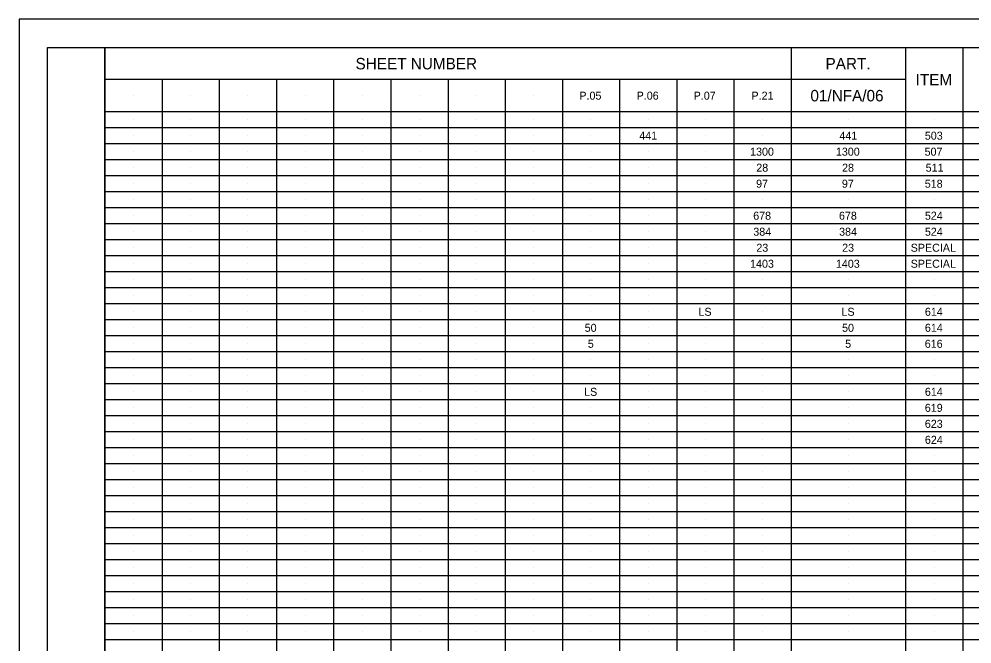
# Model space of a CAD drawing. Extents: x 0 to 34, y 0 to 22.
# Drawn here: x 0 to 16.66, y 11.07 to 22 of the extents above; entities that cross this region are included whole.
import ezdxf

# ---------------------------------------------------------------- set-up
doc = ezdxf.new("R2010")
doc.units = 0
for name, color, linetype in [('RD_P_Text', 7, 'Continuous'), ('SC_Scratch1', 7, 'Continuous'), ('SH_Border', 7, 'Continuous'), ('SH_Cut_Line', 7, 'Continuous'), ('SH_Data', 7, 'Continuous')]:
    doc.layers.add(name, color=color, linetype=linetype)

msp = doc.modelspace()

# ---------------------------------------------------------------- linework, layer by layer
at = {"layer": 'SC_Scratch1'}
for p, q in [((2, 20.66), (2, 20.66)), ((3, 20.66), (3, 20.66)), ((4, 20.66), (4, 20.66)), ((5, 20.66), (5, 20.66)), ((6, 20.66), (6, 20.66)), ((7, 20.66), (7, 20.66)), ((8, 20.66), (8, 20.66)), ((9, 20.66), (9, 20.66)), ((10, 20.66), (10, 20.66)), ((11, 20.66), (11, 20.66)), ((12, 20.66), (12, 20.66)), ((13, 20.66), (13, 20.66)), ((14.5, 20.66), (14.5, 20.66)), ((2, 20.24), (2, 20.24)), ((3, 20.24), (3, 20.24)), ((4, 20.24), (4, 20.24)), ((5, 20.24), (5, 20.24)), ((6, 20.24), (6, 20.24)), ((7, 20.24), (7, 20.24)), ((8, 20.24), (8, 20.24)), ((9, 20.24), (9, 20.24)), ((10, 20.24), (10, 20.24)), ((11, 20.24), (11, 20.24)), ((12, 20.24), (12, 20.24)), ((13, 20.24), (13, 20.24)), ((14.5, 20.24), (14.5, 20.24)), ((16, 20.24), (16, 20.24)), ((2, 19.96), (2, 19.96)), ((3, 19.96), (3, 19.96)), ((4, 19.96), (4, 19.96)), ((5, 19.96), (5, 19.96)), ((6, 19.96), (6, 19.96)), ((7, 19.96), (7, 19.96)), ((8, 19.96), (8, 19.96)), ((9, 19.96), (9, 19.96)), ((10, 19.96), (10, 19.96)), ((11, 19.96), (11, 19.96)), ((12, 19.96), (12, 19.96)), ((13, 19.96), (13, 19.96)), ((14.5, 19.96), (14.5, 19.96)), ((16, 19.96), (16, 19.96)), ((2, 19.68), (2, 19.68)), ((3, 19.68), (3, 19.68)), ((4, 19.68), (4, 19.68)), ((5, 19.68), (5, 19.68)), ((6, 19.68), (6, 19.68)), ((7, 19.68), (7, 19.68)), ((8, 19.68), (8, 19.68)), ((9, 19.68), (9, 19.68)), ((10, 19.68), (10, 19.68)), ((11, 19.68), (11, 19.68)), ((12, 19.68), (12, 19.68)), ((13, 19.68), (13, 19.68)), ((14.5, 19.68), (14.5, 19.68)), ((16, 19.68), (16, 19.68)), ((2, 19.4), (2, 19.4)), ((3, 19.4), (3, 19.4)), ((4, 19.4), (4, 19.4)), ((5, 19.4), (5, 19.4)), ((6, 19.4), (6, 19.4)), ((7, 19.4), (7, 19.4)), ((8, 19.4), (8, 19.4)), ((9, 19.4), (9, 19.4)), ((10, 19.4), (10, 19.4)), ((11, 19.4), (11, 19.4)), ((12, 19.4), (12, 19.4)), ((13, 19.4), (13, 19.4)), ((14.5, 19.4), (14.5, 19.4)), ((16, 19.4), (16, 19.4)), ((2, 19.12), (2, 19.12)), ((3, 19.12), (3, 19.12)), ((4, 19.12), (4, 19.12)), ((5, 19.12), (5, 19.12)), ((6, 19.12), (6, 19.12)), ((7, 19.12), (7, 19.12)), ((8, 19.12), (8, 19.12)), ((9, 19.12), (9, 19.12)), ((10, 19.12), (10, 19.12)), ((11, 19.12), (11, 19.12)), ((12, 19.12), (12, 19.12)), ((13, 19.12), (13, 19.12)), ((14.5, 19.12), (14.5, 19.12)), ((16, 19.12), (16, 19.12)), ((2, 18.84), (2, 18.84)), ((3, 18.84), (3, 18.84)), ((4, 18.84), (4, 18.84)), ((5, 18.84), (5, 18.84)), ((6, 18.84), (6, 18.84)), ((7, 18.84), (7, 18.84)), ((8, 18.84), (8, 18.84)), ((9, 18.84), (9, 18.84)), ((10, 18.84), (10, 18.84)), ((11, 18.84), (11, 18.84)), ((12, 18.84), (12, 18.84)), ((13, 18.84), (13, 18.84)), ((14.5, 18.84), (14.5, 18.84)), ((16, 18.84), (16, 18.84)), ((2, 18.56), (2, 18.56)), ((3, 18.56), (3, 18.56)), ((4, 18.56), (4, 18.56)), ((5, 18.56), (5, 18.56)), ((6, 18.56), (6, 18.56)), ((7, 18.56), (7, 18.56)), ((8, 18.56), (8, 18.56)), ((9, 18.56), (9, 18.56)), ((10, 18.56), (10, 18.56)), ((11, 18.56), (11, 18.56)), ((12, 18.56), (12, 18.56)), ((13, 18.56), (13, 18.56)), ((14.5, 18.56), (14.5, 18.56)), ((16, 18.56), (16, 18.56)), ((2, 18.28), (2, 18.28)), ((3, 18.28), (3, 18.28)), ((4, 18.28), (4, 18.28)), ((5, 18.28), (5, 18.28)), ((6, 18.28), (6, 18.28)), ((7, 18.28), (7, 18.28)), ((8, 18.28), (8, 18.28)), ((9, 18.28), (9, 18.28)), ((10, 18.28), (10, 18.28)), ((11, 18.28), (11, 18.28)), ((12, 18.28), (12, 18.28)), ((13, 18.28), (13, 18.28)), ((14.5, 18.28), (14.5, 18.28)), ((16, 18.28), (16, 18.28)), ((2, 18), (2, 18)), ((3, 18), (3, 18)), ((4, 18), (4, 18)), ((5, 18), (5, 18)), ((6, 18), (6, 18)), ((7, 18), (7, 18)), ((8, 18), (8, 18)), ((9, 18), (9, 18)), ((10, 18), (10, 18)), ((11, 18), (11, 18)), ((12, 18), (12, 18)), ((13, 18), (13, 18)), ((14.5, 18), (14.5, 18)), ((16, 18), (16, 18)), ((2, 17.72), (2, 17.72)), ((3, 17.72), (3, 17.72)), ((4, 17.72), (4, 17.72)), ((5, 17.72), (5, 17.72)), ((6, 17.72), (6, 17.72)), ((7, 17.72), (7, 17.72)), ((8, 17.72), (8, 17.72)), ((9, 17.72), (9, 17.72)), ((10, 17.72), (10, 17.72)), ((11, 17.72), (11, 17.72)), ((12, 17.72), (12, 17.72)), ((13, 17.72), (13, 17.72)), ((14.5, 17.72), (14.5, 17.72)), ((16, 17.72), (16, 17.72)), ((2, 17.44), (2, 17.44)), ((3, 17.44), (3, 17.44)), ((4, 17.44), (4, 17.44)), ((5, 17.44), (5, 17.44)), ((6, 17.44), (6, 17.44)), ((7, 17.44), (7, 17.44)), ((8, 17.44), (8, 17.44)), ((9, 17.44), (9, 17.44)), ((10, 17.44), (10, 17.44)), ((11, 17.44), (11, 17.44)), ((12, 17.44), (12, 17.44)), ((13, 17.44), (13, 17.44)), ((14.5, 17.44), (14.5, 17.44)), ((16, 17.44), (16, 17.44)), ((2, 17.16), (2, 17.16)), ((3, 17.16), (3, 17.16)), ((4, 17.16), (4, 17.16)), ((5, 17.16), (5, 17.16)), ((6, 17.16), (6, 17.16)), ((7, 17.16), (7, 17.16)), ((8, 17.16), (8, 17.16)), ((9, 17.16), (9, 17.16)), ((10, 17.16), (10, 17.16)), ((11, 17.16), (11, 17.16)), ((12, 17.16), (12, 17.16)), ((13, 17.16), (13, 17.16)), ((14.5, 17.16), (14.5, 17.16)), ((16, 17.16), (16, 17.16)), ((2, 16.88), (2, 16.88)), ((3, 16.88), (3, 16.88)), ((4, 16.88), (4, 16.88)), ((5, 16.88), (5, 16.88)), ((6, 16.88), (6, 16.88)), ((7, 16.88), (7, 16.88)), ((8, 16.88), (8, 16.88)), ((9, 16.88), (9, 16.88)), ((10, 16.88), (10, 16.88)), ((11, 16.88), (11, 16.88)), ((12, 16.88), (12, 16.88)), ((13, 16.88), (13, 16.88)), ((14.5, 16.88), (14.5, 16.88)), ((16, 16.88), (16, 16.88)), ((2, 16.6), (2, 16.6)), ((3, 16.6), (3, 16.6)), ((4, 16.6), (4, 16.6)), ((5, 16.6), (5, 16.6)), ((6, 16.6), (6, 16.6)), ((7, 16.6), (7, 16.6)), ((8, 16.6), (8, 16.6)), ((9, 16.6), (9, 16.6)), ((10, 16.6), (10, 16.6)), ((11, 16.6), (11, 16.6)), ((12, 16.6), (12, 16.6)), ((13, 16.6), (13, 16.6)), ((14.5, 16.6), (14.5, 16.6)), ((16, 16.6), (16, 16.6)), ((2, 16.32), (2, 16.32)), ((3, 16.32), (3, 16.32)), ((4, 16.32), (4, 16.32)), ((5, 16.32), (5, 16.32)), ((6, 16.32), (6, 16.32)), ((7, 16.32), (7, 16.32)), ((8, 16.32), (8, 16.32)), ((9, 16.32), (9, 16.32)), ((10, 16.32), (10, 16.32)), ((11, 16.32), (11, 16.32)), ((12, 16.32), (12, 16.32)), ((13, 16.32), (13, 16.32)), ((14.5, 16.32), (14.5, 16.32)), ((16, 16.32), (16, 16.32)), ((2, 16.04), (2, 16.04)), ((3, 16.04), (3, 16.04)), ((4, 16.04), (4, 16.04)), ((5, 16.04), (5, 16.04)), ((6, 16.04), (6, 16.04)), ((7, 16.04), (7, 16.04)), ((8, 16.04), (8, 16.04)), ((9, 16.04), (9, 16.04)), ((10, 16.04), (10, 16.04)), ((11, 16.04), (11, 16.04)), ((12, 16.04), (12, 16.04)), ((13, 16.04), (13, 16.04)), ((14.5, 16.04), (14.5, 16.04)), ((16, 16.04), (16, 16.04)), ((2, 15.76), (2, 15.76)), ((3, 15.76), (3, 15.76)), ((4, 15.76), (4, 15.76)), ((5, 15.76), (5, 15.76)), ((6, 15.76), (6, 15.76)), ((7, 15.76), (7, 15.76)), ((8, 15.76), (8, 15.76)), ((9, 15.76), (9, 15.76)), ((10, 15.76), (10, 15.76)), ((11, 15.76), (11, 15.76)), ((12, 15.76), (12, 15.76)), ((13, 15.76), (13, 15.76)), ((14.5, 15.76), (14.5, 15.76)), ((16, 15.76), (16, 15.76)), ((2, 15.48), (2, 15.48)), ((3, 15.48), (3, 15.48)), ((4, 15.48), (4, 15.48)), ((5, 15.48), (5, 15.48)), ((6, 15.48), (6, 15.48)), ((7, 15.48), (7, 15.48)), ((8, 15.48), (8, 15.48)), ((9, 15.48), (9, 15.48)), ((10, 15.48), (10, 15.48)), ((11, 15.48), (11, 15.48)), ((12, 15.48), (12, 15.48)), ((13, 15.48), (13, 15.48)), ((14.5, 15.48), (14.5, 15.48)), ((16, 15.48), (16, 15.48)), ((2, 15.2), (2, 15.2)), ((3, 15.2), (3, 15.2)), ((4, 15.2), (4, 15.2)), ((5, 15.2), (5, 15.2)), ((6, 15.2), (6, 15.2)), ((7, 15.2), (7, 15.2)), ((8, 15.2), (8, 15.2)), ((9, 15.2), (9, 15.2)), ((10, 15.2), (10, 15.2)), ((11, 15.2), (11, 15.2)), ((12, 15.2), (12, 15.2)), ((13, 15.2), (13, 15.2)), ((14.5, 15.2), (14.5, 15.2)), ((16, 15.2), (16, 15.2)), ((2, 14.92), (2, 14.92)), ((3, 14.92), (3, 14.92)), ((4, 14.92), (4, 14.92)), ((5, 14.92), (5, 14.92)), ((6, 14.92), (6, 14.92)), ((7, 14.92), (7, 14.92)), ((8, 14.92), (8, 14.92)), ((9, 14.92), (9, 14.92)), ((10, 14.92), (10, 14.92)), ((11, 14.92), (11, 14.92)), ((12, 14.92), (12, 14.92)), ((13, 14.92), (13, 14.92)), ((14.5, 14.92), (14.5, 14.92)), ((16, 14.92), (16, 14.92)), ((2, 14.64), (2, 14.64)), ((3, 14.64), (3, 14.64)), ((4, 14.64), (4, 14.64)), ((5, 14.64), (5, 14.64)), ((6, 14.64), (6, 14.64)), ((7, 14.64), (7, 14.64)), ((8, 14.64), (8, 14.64)), ((9, 14.64), (9, 14.64)), ((10, 14.64), (10, 14.64)), ((11, 14.64), (11, 14.64)), ((12, 14.64), (12, 14.64)), ((13, 14.64), (13, 14.64)), ((14.5, 14.64), (14.5, 14.64)), ((16, 14.64), (16, 14.64)), ((2, 14.36), (2, 14.36)), ((3, 14.36), (3, 14.36)), ((4, 14.36), (4, 14.36)), ((5, 14.36), (5, 14.36)), ((6, 14.36), (6, 14.36)), ((7, 14.36), (7, 14.36)), ((8, 14.36), (8, 14.36)), ((9, 14.36), (9, 14.36)), ((10, 14.36), (10, 14.36)), ((11, 14.36), (11, 14.36)), ((12, 14.36), (12, 14.36)), ((13, 14.36), (13, 14.36)), ((14.5, 14.36), (14.5, 14.36)), ((16, 14.36), (16, 14.36)), ((2, 14.08), (2, 14.08)), ((3, 14.08), (3, 14.08)), ((4, 14.08), (4, 14.08)), ((5, 14.08), (5, 14.08)), ((6, 14.08), (6, 14.08)), ((7, 14.08), (7, 14.08)), ((8, 14.08), (8, 14.08)), ((9, 14.08), (9, 14.08)), ((10, 14.08), (10, 14.08)), ((11, 14.08), (11, 14.08)), ((12, 14.08), (12, 14.08)), ((13, 14.08), (13, 14.08)), ((14.5, 14.08), (14.5, 14.08)), ((16, 14.08), (16, 14.08)), ((2, 13.8), (2, 13.8)), ((3, 13.8), (3, 13.8)), ((4, 13.8), (4, 13.8)), ((5, 13.8), (5, 13.8)), ((6, 13.8), (6, 13.8)), ((7, 13.8), (7, 13.8)), ((8, 13.8), (8, 13.8)), ((9, 13.8), (9, 13.8)), ((10, 13.8), (10, 13.8)), ((11, 13.8), (11, 13.8)), ((12, 13.8), (12, 13.8)), ((13, 13.8), (13, 13.8)), ((14.5, 13.8), (14.5, 13.8)), ((16, 13.8), (16, 13.8)), ((2, 13.52), (2, 13.52)), ((3, 13.52), (3, 13.52)), ((4, 13.52), (4, 13.52)), ((5, 13.52), (5, 13.52)), ((6, 13.52), (6, 13.52)), ((7, 13.52), (7, 13.52)), ((8, 13.52), (8, 13.52)), ((9, 13.52), (9, 13.52)), ((10, 13.52), (10, 13.52)), ((11, 13.52), (11, 13.52)), ((12, 13.52), (12, 13.52)), ((13, 13.52), (13, 13.52)), ((14.5, 13.52), (14.5, 13.52)), ((16, 13.52), (16, 13.52)), ((2, 13.24), (2, 13.24)), ((3, 13.24), (3, 13.24)), ((4, 13.24), (4, 13.24)), ((5, 13.24), (5, 13.24)), ((6, 13.24), (6, 13.24)), ((7, 13.24), (7, 13.24)), ((8, 13.24), (8, 13.24)), ((9, 13.24), (9, 13.24)), ((10, 13.24), (10, 13.24)), ((11, 13.24), (11, 13.24)), ((12, 13.24), (12, 13.24)), ((13, 13.24), (13, 13.24)), ((14.5, 13.24), (14.5, 13.24)), ((16, 13.24), (16, 13.24)), ((2, 12.96), (2, 12.96)), ((3, 12.96), (3, 12.96)), ((4, 12.96), (4, 12.96)), ((5, 12.96), (5, 12.96)), ((6, 12.96), (6, 12.96)), ((7, 12.96), (7, 12.96)), ((8, 12.96), (8, 12.96)), ((9, 12.96), (9, 12.96)), ((10, 12.96), (10, 12.96)), ((11, 12.96), (11, 12.96)), ((12, 12.96), (12, 12.96)), ((13, 12.96), (13, 12.96)), ((14.5, 12.96), (14.5, 12.96)), ((16, 12.96), (16, 12.96)), ((2, 12.68), (2, 12.68)), ((3, 12.68), (3, 12.68)), ((4, 12.68), (4, 12.68)), ((5, 12.68), (5, 12.68)), ((6, 12.68), (6, 12.68)), ((7, 12.68), (7, 12.68)), ((8, 12.68), (8, 12.68)), ((9, 12.68), (9, 12.68)), ((10, 12.68), (10, 12.68)), ((11, 12.68), (11, 12.68)), ((12, 12.68), (12, 12.68)), ((13, 12.68), (13, 12.68)), ((14.5, 12.68), (14.5, 12.68)), ((16, 12.68), (16, 12.68)), ((2, 12.4), (2, 12.4)), ((3, 12.4), (3, 12.4)), ((4, 12.4), (4, 12.4)), ((5, 12.4), (5, 12.4)), ((6, 12.4), (6, 12.4)), ((7, 12.4), (7, 12.4)), ((8, 12.4), (8, 12.4)), ((9, 12.4), (9, 12.4)), ((10, 12.4), (10, 12.4)), ((11, 12.4), (11, 12.4)), ((12, 12.4), (12, 12.4)), ((13, 12.4), (13, 12.4)), ((14.5, 12.4), (14.5, 12.4)), ((16, 12.4), (16, 12.4)), ((2, 12.12), (2, 12.12)), ((3, 12.12), (3, 12.12)), ((4, 12.12), (4, 12.12)), ((5, 12.12), (5, 12.12)), ((6, 12.12), (6, 12.12)), ((7, 12.12), (7, 12.12)), ((8, 12.12), (8, 12.12)), ((9, 12.12), (9, 12.12)), ((10, 12.12), (10, 12.12)), ((11, 12.12), (11, 12.12)), ((12, 12.12), (12, 12.12)), ((13, 12.12), (13, 12.12)), ((14.5, 12.12), (14.5, 12.12)), ((16, 12.12), (16, 12.12)), ((2, 11.84), (2, 11.84)), ((3, 11.84), (3, 11.84)), ((4, 11.84), (4, 11.84)), ((5, 11.84), (5, 11.84)), ((6, 11.84), (6, 11.84)), ((7, 11.84), (7, 11.84)), ((8, 11.84), (8, 11.84)), ((9, 11.84), (9, 11.84)), ((10, 11.84), (10, 11.84)), ((11, 11.84), (11, 11.84)), ((12, 11.84), (12, 11.84)), ((13, 11.84), (13, 11.84)), ((14.5, 11.84), (14.5, 11.84)), ((16, 11.84), (16, 11.84)), ((2, 11.56), (2, 11.56)), ((3, 11.56), (3, 11.56)), ((4, 11.56), (4, 11.56)), ((5, 11.56), (5, 11.56)), ((6, 11.56), (6, 11.56)), ((7, 11.56), (7, 11.56)), ((8, 11.56), (8, 11.56)), ((9, 11.56), (9, 11.56)), ((10, 11.56), (10, 11.56)), ((11, 11.56), (11, 11.56)), ((12, 11.56), (12, 11.56)), ((13, 11.56), (13, 11.56)), ((14.5, 11.56), (14.5, 11.56)), ((16, 11.56), (16, 11.56)), ((2, 11.28), (2, 11.28)), ((3, 11.28), (3, 11.28)), ((4, 11.28), (4, 11.28)), ((5, 11.28), (5, 11.28)), ((6, 11.28), (6, 11.28)), ((7, 11.28), (7, 11.28)), ((8, 11.28), (8, 11.28)), ((9, 11.28), (9, 11.28)), ((10, 11.28), (10, 11.28)), ((11, 11.28), (11, 11.28)), ((12, 11.28), (12, 11.28)), ((13, 11.28), (13, 11.28)), ((14.5, 11.28), (14.5, 11.28)), ((16, 11.28), (16, 11.28))]:
    msp.add_line(p, q, dxfattribs=at)
at = {"layer": 'SH_Border'}
for points in [[(0.5, 21.5), (1.5, 21.5), (1.5, 0.5), (0.5, 0.5)], [(1.5, 21.5), (33.5, 21.5), (33.5, 0.5), (1.5, 0.5)]]:
    msp.add_lwpolyline(points, close=True, dxfattribs=at)
at = {"layer": 'SH_Cut_Line'}
msp.add_lwpolyline([(0, 0), (34, 0), (34, 22), (0, 22)], close=True, dxfattribs=at)
at = {"layer": 'SH_Data'}
for p, q in [((13.5, 21.5), (13.5, 0.5)), ((15.5, 21.5), (15.5, 0.5)), ((16.5, 21.5), (16.5, 0.5)), ((15.5, 20.94), (1.5, 20.94)), ((2.5, 20.94), (2.5, 0.5)), ((3.5, 20.94), (3.5, 0.5)), ((4.5, 20.94), (4.5, 0.5)), ((5.5, 20.94), (5.5, 0.5)), ((6.5, 20.94), (6.5, 0.5)), ((7.5, 20.94), (7.5, 0.5)), ((8.5, 20.94), (8.5, 0.5)), ((9.5, 20.94), (9.5, 0.5)), ((10.5, 20.94), (10.5, 0.5)), ((11.5, 20.94), (11.5, 0.5)), ((12.5, 20.94), (12.5, 0.5)), ((13.5, 20.94), (13.5, 0.5)), ((32, 20.38), (1.5, 20.38)), ((32, 20.1), (1.5, 20.1)), ((32, 19.82), (1.5, 19.82)), ((32, 19.54), (1.5, 19.54)), ((32, 19.26), (1.5, 19.26)), ((32, 18.98), (1.5, 18.98)), ((32, 18.7), (1.5, 18.7)), ((32, 18.42), (1.5, 18.42)), ((32, 18.14), (1.5, 18.14)), ((32, 17.86), (1.5, 17.86)), ((32, 17.58), (1.5, 17.58)), ((32, 17.3), (1.5, 17.3)), ((32, 17.02), (1.5, 17.02)), ((32, 16.74), (1.5, 16.74)), ((32, 16.46), (1.5, 16.46)), ((32, 16.18), (1.5, 16.18)), ((32, 15.9), (1.5, 15.9)), ((32, 15.62), (1.5, 15.62)), ((32, 15.34), (1.5, 15.34)), ((32, 15.06), (1.5, 15.06)), ((32, 14.78), (1.5, 14.78)), ((32, 14.5), (1.5, 14.5)), ((32, 14.22), (1.5, 14.22)), ((32, 13.94), (1.5, 13.94)), ((32, 13.66), (1.5, 13.66)), ((32, 13.38), (1.5, 13.38)), ((32, 13.1), (1.5, 13.1)), ((32, 12.82), (1.5, 12.82)), ((32, 12.54), (1.5, 12.54)), ((32, 12.26), (1.5, 12.26)), ((32, 11.98), (1.5, 11.98)), ((32, 11.7), (1.5, 11.7)), ((32, 11.42), (1.5, 11.42)), ((32, 11.14), (1.5, 11.14))]:
    msp.add_line(p, q, dxfattribs=at)

# ---------------------------------------------------------------- texts
at = {"layer": 'RD_P_Text'}
for s, p in [('P.05', (9.797, 20.59)), ('P.06', (10.798, 20.59)), ('P.07', (11.795, 20.59)), ('P.21', (12.806, 20.59)), ('441', (10.844, 19.89)), ('441', (14.344, 19.89)), ('503', (15.837, 19.89)), ('1300', (12.782, 19.61)), ('1300', (14.282, 19.61)), ('507', (15.833, 19.61)), ('28', (12.89, 19.33)), ('28', (14.39, 19.33)), ('511', (15.852, 19.33)), ('97', (12.887, 19.05)), ('97', (14.387, 19.05)), ('518', (15.836, 19.05)), ('678', (12.836, 18.49)), ('678', (14.336, 18.49)), ('524', (15.838, 18.49)), ('384', (12.838, 18.21)), ('384', (14.338, 18.21)), ('524', (15.838, 18.21)), ('23', (12.891, 17.93)), ('23', (14.391, 17.93)), ('SPECIAL', (15.59, 17.93)), ('1403', (12.782, 17.65)), ('1403', (14.282, 17.65)), ('SPECIAL', (15.59, 17.65)), ('LS', (11.88, 16.81)), ('LS', (14.38, 16.81)), ('614', (15.838, 16.81)), ('50', (9.89, 16.53)), ('50', (14.39, 16.53)), ('614', (15.838, 16.53)), ('5', (9.944, 16.25)), ('5', (14.444, 16.25)), ('616', (15.836, 16.25)), ('LS', (9.88, 15.41)), ('614', (15.838, 15.41)), ('619', (15.837, 15.13)), ('623', (15.837, 14.85)), ('624', (15.838, 14.57))]:
    msp.add_text(s, height=0.14, dxfattribs=at).set_placement(p)
at = {"layer": 'SH_Data'}
for s, p in [('SHEET NUMBER', (5.883, 21.12)), ('PART.', (14.101, 21.12)), ('ITEM', (15.676, 20.84)), ('01/NFA/06', (13.837, 20.56))]:
    msp.add_text(s, height=0.2, dxfattribs=at).set_placement(p)

doc.saveas('drawing.dxf')
